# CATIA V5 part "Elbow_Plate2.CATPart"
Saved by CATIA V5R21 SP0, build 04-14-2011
Part number: Elbow_Plate2
Bounding box of the stored display mesh (mm): x 0 to 3, y -50.316 to 4.684, z -50.993 to 11
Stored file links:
  F:\教程\Robotic_Arm_Arduino_Kinect\机械臂CAD\Arm_Detailed_Design\Elbow_Plate2.CATPart
  C:\Users\Administrator\Desktop\arm\plate1.CATPart
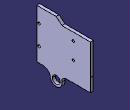
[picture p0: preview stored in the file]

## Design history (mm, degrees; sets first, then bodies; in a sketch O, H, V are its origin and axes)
Body1 (main body)
  Sketch1 on yz-plane, origin (0, 0, 0), H (0, 1, 0), V (0, 0, 1)
    line L1 (4.6838, 6) -> (-24.3574, 6)
    line L2 (-50.3162, -0.2265) -> (-50.3162, -39)
    line L3 (-20.5182, -39) -> (5.4818, -39)
    line L4 (4.6838, -25.3859) -> (4.6838, 6)
    point P3 (-50.3162, -39)
    circle A1 centre (-30.3162, -45) radius 4
    point P4 (-30.3162, -45)
    arc A2 centre (-30.3162, -45) radius 6 from (-24.4374, -43.8) to (-36.2546, -45.8571) cw
    arc A3 centre (-20.5182, -43) radius 4 from (-24.4374, -43.8) to (-20.5182, -39) cw
    line L5 (-50.3162, -39) -> (-44.1726, -39)
    arc A4 centre (-44.1726, -47) radius 8 from (-36.2546, -45.8571) to (-44.1726, -39) ccw
    line L6 (-50.3162, -0.2265) -> (-50.3162, 11)
    line L7 (-50.3162, 11) -> (-30.3162, 11)
    line L8 (-30.3162, 11) -> (-24.3574, 6)
    line L9 (4.6838, -25.3859) -> (4.6838, -39)
    point P16 (4.6838, -39)
    line L10 (4.6838, -39) -> (5.4818, -39)
    axis line L11 (-22.0185, 29.2882) -> (-22.0185, -102.7112)
    circle A5 centre (-47.8162, -4) radius 1.25
    point P19 (-47.8162, -4)
    circle A6 centre (-47.8162, -24) radius 1.25
    point P20 (-47.8162, -24)
    circle A7 centre (-12.8162, -2) radius 1.25
    point P21 (-12.8162, -2)
    circle A8 centre (-12.8162, -19) radius 1.25
    point P22 (-12.8162, -19)
    distance L2 L4 = 55
    radius A1 = 4
    radius A2 = 6
    radius A3 = 4
    radius A4 = 8
    distance P4 H = 45
    distance L1 L3 = 45
    distance L2 P4 = 20
    length L3 = 26
    distance L7 L5 = 50
    angle L8 L7 = 140
    length L7 = 20
    distance P20 L5 = 15
    distance P19 L7 = 15
    radius A6 = 1.25
    radius A5 = 1.25
    distance P19 L2 = 2.5
    distance P20 L2 = 2.5
    radius A7 = 1.25
    distance P21 L1 = 8
    distance P21 L2 = 37.5
    radius A8 = 1.25
    distance P22 L2 = 37.5
    distance L1 P22 = 25
    horizontal: L1 H, L3 H, L7 H
    vertical: L2 V, L4 V, L6 V, L9 V, L11 V
    tangency: A2 L3, A3 A2, A3 L3, L5 A2, A4 A2, A4 L5, L10 A2
    coincidence: L3 P3, P16 L3
    fix: L4
  Pad1: profile Sketch1, direction (1, 0, 0), length 3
